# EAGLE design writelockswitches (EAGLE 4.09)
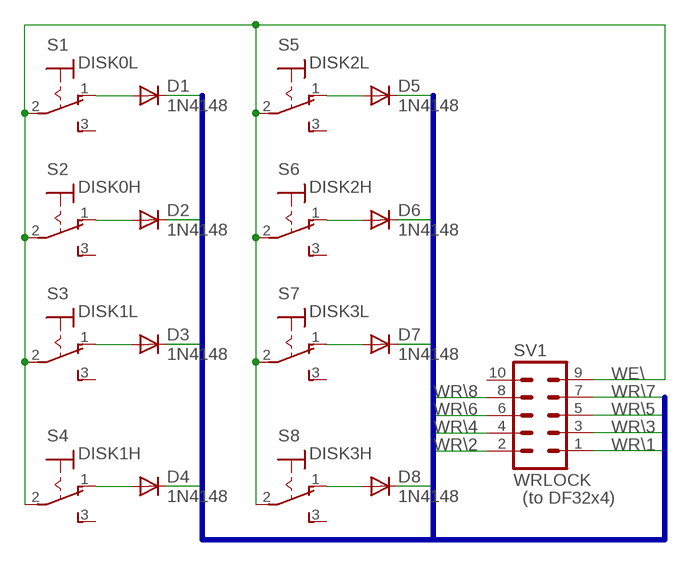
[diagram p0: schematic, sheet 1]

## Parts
D1  1N4148  [DO35-10]
D2  1N4148  [DO35-10]
D3  1N4148  [DO35-10]
D4  1N4148  [DO35-10]
D5  1N4148  [DO35-10]
D6  1N4148  [DO35-10]
D7  1N4148  [DO35-10]
D8  1N4148  [DO35-10]
S1  DISK0L  320-916  [320-916]
S2  DISK0H  320-916  [320-916]
S3  DISK1L  320-916  [320-916]
S4  DISK1H  320-916  [320-916]
S5  DISK2L  320-916  [320-916]
S6  DISK2H  320-916  [320-916]
S7  DISK3L  320-916  [320-916]
S8  DISK3H  320-916  [320-916]
SV1  WRLOCK  MA05-2  [MA05-2]

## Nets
N$1: D1.A S1.1(O)
N$2: D2.A S2.1(O)
N$3: D3.A S3.1(O)
N$4: D4.A S4.1(O)
N$5: D5.A S5.1(O)
N$6: D6.A S6.1(O)
N$7: D7.A S7.1(O)
N$8: D8.A S8.1(O)
WE\: S1.2(P) S2.2(P) S3.2(P) S4.2(P) S5.2(P) S6.2(P) S7.2(P) S8.2(P) SV1.9
WR\1: D1.C SV1.1
WR\2: D2.C SV1.2
WR\3: D3.C SV1.3
WR\4: D4.C SV1.4
WR\5: D5.C SV1.5
WR\6: D6.C SV1.6
WR\7: D7.C SV1.7
WR\8: D8.C SV1.8
Unconnected: S1.3(S) S2.3(S) S3.3(S) S4.3(S) S5.3(S) S6.3(S) S7.3(S) S8.3(S) SV1.10

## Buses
WR\[1..8]

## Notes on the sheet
- (to DF32x4)

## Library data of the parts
D1-D8 = diode:1N4148: DIODE
S1-S8 = switch:320-916: TOGGLE SWITCH distributor RS Components
SV1 = con-lstb:MA05-2: PIN HEADER

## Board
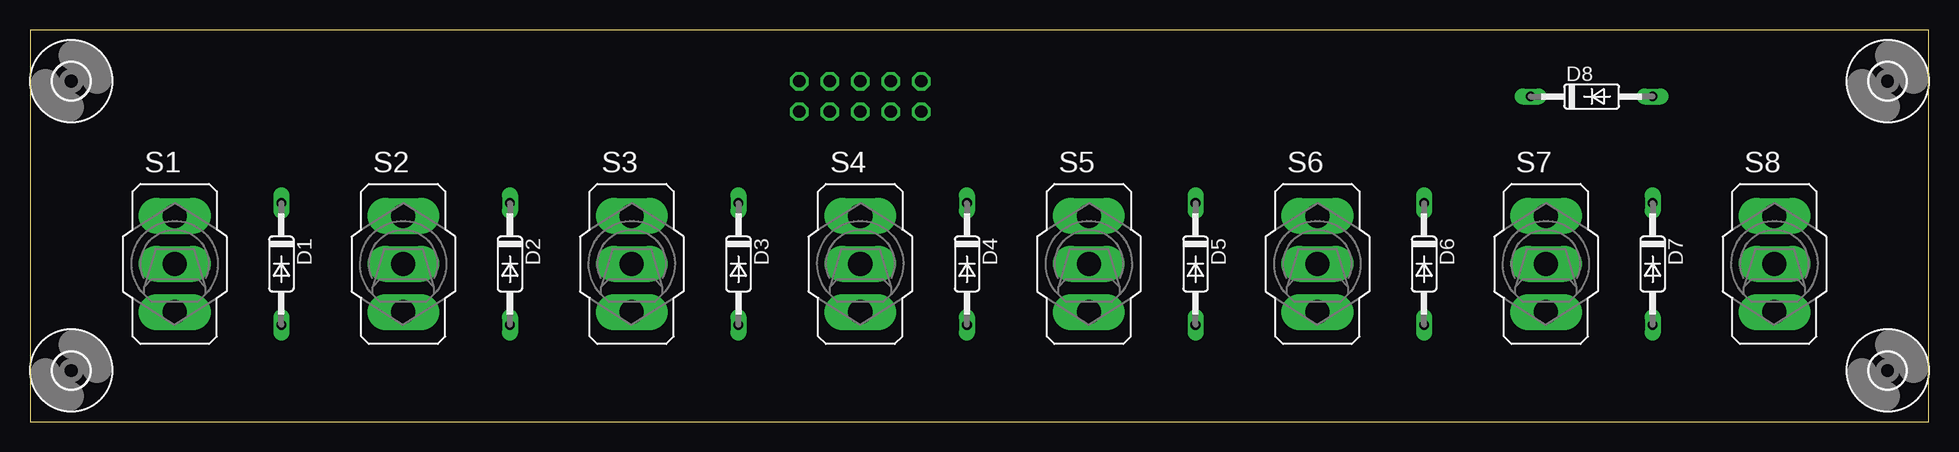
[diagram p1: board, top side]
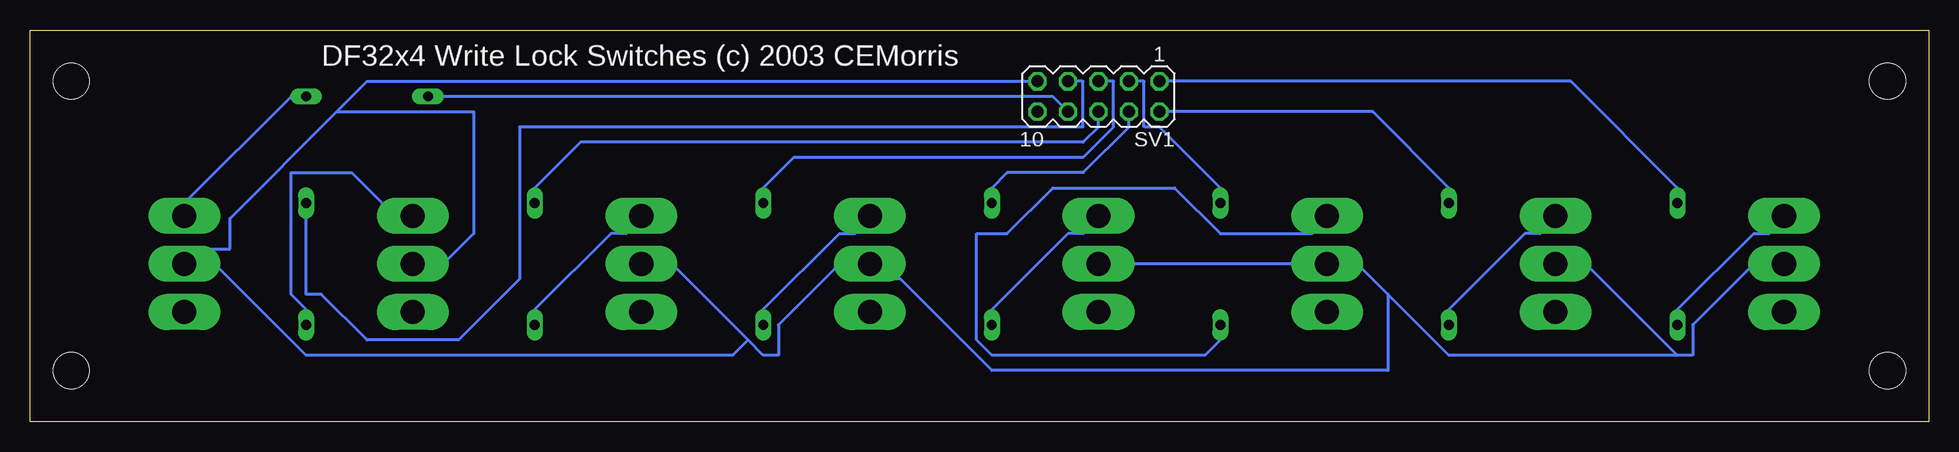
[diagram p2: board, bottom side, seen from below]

Size 158.27 x 32.69 mm. Coordinates in mm from the lower left corner, seen from the top.
Outline: 0,0 158.27,0 158.27,32.69 0,32.69 0,0
Copper layers used: Top, Bottom

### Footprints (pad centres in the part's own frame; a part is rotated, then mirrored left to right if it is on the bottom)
DO35-10 = drill 0.813 long: A 5.08,0; C -5.08,0
320-916 = drill 2.007 long: 1 0,4.013; 2 0,0; 3 0,-4.013
MA05-2 = drill 1.016 octagon: 1 -5.08,-1.27; 2 -5.08,1.27; 3 -2.54,-1.27; 4 -2.54,1.27; 5 0,-1.27; 6 0,1.27; 7 2.54,-1.27; 8 2.54,1.27; 9 5.08,-1.27; 10 5.08,1.27
3,0 = hole 3: 0,0

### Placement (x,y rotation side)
D1  20.95,13.17 270 top
D2  40,13.17 270 top
D3  59.05,13.17 270 top
D4  78.1,13.17 270 top
D5  97.15,13.17 270 top
D6  116.2,13.17 270 top
D7  135.25,13.17 270 top
D8  130.17,27.14 0 top
S1  12.06,13.17 0 top
S2  31.11,13.17 0 top
S3  50.16,13.17 0 top
S4  69.21,13.17 0 top
S5  88.26,13.17 0 top
S6  107.31,13.17 0 top
S7  126.36,13.17 0 top
S8  145.41,13.17 0 top
SV1  69.21,27.14 180 bottom
U$1  [3,0]  3.44,28.41 0 top
U$2  [3,0]  3.44,4.28 0 top
U$3  [3,0]  154.84,28.41 0 top
U$4  [3,0]  154.84,4.28 0 top

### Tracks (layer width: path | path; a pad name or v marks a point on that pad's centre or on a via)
N$1
  Bottom 0.254: D1.A 20.95,9.36 14.6,15.71 13.33,15.71 S1.1
N$2
  Bottom 0.254: D2.A 40,9.36 33.65,15.71 32.38,15.71 S2.1
N$3
  Bottom 0.254: D3.A 59.05,6.82 60.32,5.55 78.1,5.55 79.37,6.82 79.37,15.71 76.83,15.71 73.02,19.52 62.86,19.52 59.05,15.71 51.43,15.71 S3.1
N$4
  Bottom 0.254: D4.A 78.1,9.36 71.75,15.71 70.48,15.71 S4.1
N$5
  Bottom 0.254: D5.A 97.15,9.36 90.8,15.71 89.53,15.71 S5.1
N$6
  Bottom 0.254: D6.A 116.2,9.36 109.85,15.71 108.58,15.71 S6.1
N$7
  Bottom 0.254: D7.A 135.25,9.36 136.52,10.63 136.52,20.79 131.44,20.79 128.9,18.25 S7.1
N$8
  Bottom 0.254: D8.A 136.52,27.14 145.41,18.25 S8.1
N$9
  pour Top: 66.03,25.87 66.03,26.12 66.42,26.5 66.92,26.5 67.3,26.12 67.3,25.62 66.92,25.23 66.42,25.23 66.03,25.62
N$10
  pour Top: 63.5,28.41 63.5,28.66 63.88,29.04 64.38,29.04 64.77,28.66 64.77,28.16 64.38,27.77 63.88,27.77 63.5,28.16
N$11
  pour Top: 63.5,25.87 63.5,26.12 63.88,26.5 64.38,26.5 64.77,26.12 64.77,25.62 64.38,25.23 63.88,25.23 63.5,25.62
N$12
  pour Top: 66.03,28.41 66.03,28.66 66.42,29.04 66.92,29.04 67.3,28.66 67.3,28.16 66.92,27.77 66.42,27.77 66.03,28.16
N$13
  pour Top: 68.58,28.41 68.58,28.66 68.96,29.04 69.46,29.04 69.84,28.66 69.84,28.16 69.46,27.77 68.96,27.77 68.58,28.16
N$14
  pour Top: 71.11,28.41 71.11,28.66 71.5,29.04 72,29.04 72.39,28.66 72.39,28.16 72,27.77 71.5,27.77 71.24,28.03 71.11,28.16
N$15
  pour Top: 73.66,28.54 73.66,28.66 74.04,29.04 74.54,29.04 74.92,28.66 74.92,28.16 74.54,27.77 74.04,27.77 73.66,28.16 73.66,28.41
N$16
  pour Top: 68.58,25.87 68.58,26.12 68.96,26.5 69.46,26.5 69.84,26.12 69.84,25.62 69.46,25.23 68.96,25.23 68.7,25.49 68.58,25.62
N$17
  pour Top: 71.11,26.12 71.5,26.5 72,26.5 72.39,26.12 72.39,25.62 72,25.23 71.5,25.23 71.11,25.62
N$18
  pour Top: 73.66,25.87 73.66,26.12 74.04,26.5 74.54,26.5 74.92,26.12 74.92,25.62 74.54,25.23 74.04,25.23 73.66,25.62
WE\
  Bottom 0.254: S4.2 S3.2 47.62,13.17 45.08,10.63 | 20.95,5.55 19.68,5.55 19.68,8.09 14.6,13.17 S1.2 | 20.95,5.55 28.57,13.17 S2.2 | 45.08,10.63 40,5.55 20.95,5.55 | 98.42,6.82 104.77,13.17 S6.2 | 98.42,6.82 97.15,5.55 95.88,5.55 95.88,8.09 90.8,13.17 S5.2 86.99,11.9 85.72,11.9 78.1,4.28 45.08,4.28 45.08,10.63 | SV1.9 130.17,28.41 132.71,25.87 | 132.71,25.87 141.6,16.98 141.6,14.44 144.14,14.44 S8.2 142.87,13.17 135.25,5.55 99.69,5.55 98.42,6.82 | 132.71,25.87 121.28,25.87 121.28,15.71 123.82,13.17 S7.2
WR\1
  Bottom 0.254: SV1.1 29.84,28.41 20.95,19.52 D1.C
WR\2
  Bottom 0.254: SV1.2 46.35,25.87 40,19.52 D2.C
WR\3
  Bottom 0.254: SV1.3 65.4,28.41 65.4,24.6 64.13,24.6 59.05,19.52 D3.C
WR\4
  Bottom 0.254: SV1.4 66.67,24.6 70.48,20.79 76.83,20.79 78.1,19.52 D4.C
WR\5
  Bottom 0.254: SV1.5 67.94,28.41 67.94,24.6 70.48,22.06 94.61,22.06 97.15,19.52 D5.C
WR\6
  Bottom 0.254: SV1.6 69.21,24.6 70.48,23.33 112.39,23.33 116.2,19.52 D6.C
WR\7
  Bottom 0.254: SV1.7 70.48,28.41 70.48,24.6 117.47,24.6 117.47,11.9 122.55,6.82 130.17,6.82 133.98,10.63 135.25,10.63 D7.C
WR\8
  Bottom 0.254: SV1.8 73.02,27.14 D8.C

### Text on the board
bPlace: DF32x4 Write Lock Switches (c) 2003 CEMorris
